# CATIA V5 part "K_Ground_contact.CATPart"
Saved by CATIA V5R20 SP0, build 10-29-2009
Part number: Ground_contact
Bounding box of the stored display mesh (mm): x -21.783 to 21.783, y 49.915 to 69.604, z -962.735 to -922.735
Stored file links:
  G:\Khaled_CFAO_2011\SIL\SIL_GR2\ctanaphiko\Khaled\CAD_ThinkMOTION\K_Ground_contact.CATPart
  G:\Khaled_CFAO_2011\SIL\SIL_GR2\ctanaphiko\CATIA\Conception_Tripod.CATProduct
  G:\Khaled_CFAO_2011\SIL\SIL_GR2\ctanaphiko\CATIA\Squelette.CATPart
  G:\Khaled_CFAO_2011\SIL\SIL_GR2\ctanaphiko\Khaled\CAD_ThinkMOTION\K_Leg_Level3.CATPart
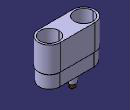
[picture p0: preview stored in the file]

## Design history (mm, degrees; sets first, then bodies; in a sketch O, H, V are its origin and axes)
External parameters (linked from other documents)
  External.Dia_Leg_Step3 = 14.3 mm
AxisSystem1: origin (0, 0, 0), X (1, 0, 0), Y (0, 1, 0), Z (0, 0, 1)
Set1
  Plane1 "Plane_end_Leg3": linked copy from another document
  Point1: linked copy from another document
  Point2: linked copy from another document
  DatumCurve1: linked copy from another document
  DatumCurve2: linked copy from another document
  Line1: linked copy from another document
  DatumPoint1: linked copy from another document
  DatumPoint2: linked copy from another document
Body1 (main body)
  Sketch1 on Plane1, origin (0, 0, -942.7345), H (1, 0, 0), V (0, 1, 0)
    construction line L1 (-13.2127, 61.024) -> (13.2127, 61.024)
    point P1 (-13.2127, 61.024)
    point P2 (13.2127, 61.024)
    line L2 (-13.2127, 69.604) -> (13.2127, 69.604)
    line L3 (13.2127, 52.444) -> (-13.2127, 52.444)
    arc A1 centre (13.2127, 61.024) radius 8.58 from (13.2127, 69.604) to (13.2127, 52.444) cw
    arc A2 centre (-13.2127, 61.024) radius 8.58 from (-13.2127, 52.444) to (-13.2127, 69.604) cw
    reference projected point E1 (13.2127, 61.024) from Point1
    reference projected point E2 (-13.2127, 61.024) from Point2
    projected circle E3 centre (-13.2127, 61.024) radius 7.15 from edge of DatumCurve1
    projected circle E4 centre (13.2127, 61.024) radius 7.15 from edge of DatumCurve2
    distance L1 L2 = 8.58 {= External.Dia_Leg_Step3 /2*1.2}
    horizontal: L1 H
    tangency: A1 L2, A2 L2, A1 L3, A2 L3
    coincidence: P2 E1, P1 E2
  Sketch2 on Plane1, origin (0, 0, -942.7345), H (1, 0, 0), V (0, 1, 0)
    construction line L1 (-13.2127, 61.024) -> (13.2127, 61.024)
    point P1 (-13.2127, 61.024)
    point P2 (13.2127, 61.024)
    line L2 (-13.2127, 68.889) -> (13.2127, 68.889)
    line L3 (13.2127, 53.159) -> (-13.2127, 53.159)
    arc A1 centre (13.2127, 61.024) radius 7.865 from (13.2127, 68.889) to (13.2127, 53.159) cw
    arc A2 centre (-13.2127, 61.024) radius 7.865 from (-13.2127, 53.159) to (-13.2127, 68.889) cw
    reference projected point E1 (13.2127, 61.024) from Point1
    reference projected point E2 (-13.2127, 61.024) from Point2
    distance L1 L2 = 7.865 {= External.Dia_Leg_Step3 /2*1.1}
    horizontal: L1 H
    tangency: A1 L2, A2 L2, A1 L3, A2 L3
    coincidence: P2 E1, P1 E2
  Pad1: profile Sketch1, direction (0, 0, 1), length 20
  Pad2: profile Sketch2, direction (0, 0, -1), length 10
  Sketch3 on Plane1, origin (0, 0, -942.7345), H (1, 0, 0), V (0, 1, 0)
    circle A1 centre (0, 65.314) radius 2.145
    point P1 (0, 65.314)
    circle A2 centre (0, 65.314) radius 2.86
    reference projected line E1 (13.2127, 69.604) -> (-13.2127, 69.604) from edge [face of Pad2 | end face of Pad1]
    reference projected line E2 (-13.2127, 52.444) -> (13.2127, 52.444) from edge [face of Pad2 | end face of Pad1]
    reference projected line E3 (-11.5019, 61.024) -> (11.5019, 61.024) from Line1
    radius A1 = 2.145 {= External.Dia_Leg_Step3*0.15}
    radius A2 = 2.86 {= External.Dia_Leg_Step3  *0.2}
    distance E1 E2 = 17.16 (reference)
    distance P1 E3 = 4.29 {= Sketch3.distance(E1 E2) /4}
    coincidence: P1 V
  Pad3: profile Sketch3, direction (0, 0, -1), length 15
  Line2: type PtPt, FirstPoint DatumPoint1, SecondPoint DatumPoint2
  CircPattern1: of Pad3, instances 2, angular step 45, axis from Line2
  Chamfer1: length 0.25, angle 45, on edge [start face of Pad1 | face of Pad1 from Sketch1.A2]
  Sketch4 on Plane1, origin (0, 0, -942.7345), H (1, 0, 0), V (0, 1, 0)
    point P1 (0, 65.314)
    circle A1 centre (0, 65.314) radius 2.145
    reference projected line E1 (13.2127, 69.604) -> (-13.2127, 69.604) from edge [face of Pad2 | end face of Pad1]
    reference projected line E2 (-13.2127, 52.444) -> (13.2127, 52.444) from edge [face of Pad2 | end face of Pad1]
    reference projected line E3 (-11.5019, 61.024) -> (11.5019, 61.024) from Line1
    radius A1 = 2.145 {= External.Dia_Leg_Step3 *0.15}
    distance E1 E2 = 17.16 (reference)
    distance P1 E3 = 4.29 {= Sketch4.distance(E1 E2) /4}
    coincidence: P1 V
  Pad4: profile Sketch4, direction (0, 0, -1), length 20
  Chamfer2: length 2.145 {= External.Dia_Leg_Step3 *0.15}, angle 45, on edge [end face of Pad4 | face of Pad4 from Sketch4.A1]
  CircPattern2: of Pad4, Chamfer2, instances 2, angular step 45, axis from Line2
